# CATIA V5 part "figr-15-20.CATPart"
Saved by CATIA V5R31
Part number: Part1
Bounding box of the stored display mesh (mm): x -81.56 to 85.56, y -36.965 to 25.965, z 0 to 42
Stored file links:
  D:\PROJECTS\Project 2021\US EDITION\CATIA V5 6R 2021\Resources\Part Files\c15_catia_v5_6r2021_prt\figr-15-20.CATPart
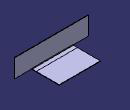
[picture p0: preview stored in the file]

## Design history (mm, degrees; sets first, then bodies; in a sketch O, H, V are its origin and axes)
SheetMetalParameters1: Thickness 1, BendRadius 1, KFactor 0.325257 {= log(min(100,max(20*SheetMetalParameters1.BendRadius,SheetMetalParameters1.Thickness)/SheetMetalParameters1.Thickness))/log(100)/2}, ReliefRadialLength 1, ReliefAxialLength 2, MinimumBendRadius 0
Body1 (main body)
  Sketch1 on xy-plane, origin (0, 0, 0), H (1, 0, 0), V (0, 1, 0)
    line L1 (-46.5596, 25.9646) -> (46.5596, 25.9646)
    line L2 (46.5596, 25.9646) -> (46.5596, -25.9646)
    line L3 (46.5596, -25.9646) -> (-46.5596, -25.9646)
    line L4 (-46.5596, -25.9646) -> (-46.5596, 25.9646)
    horizontal: L1 H, L3 H
    vertical: L2 V, L4 V
    symmetry: L1 L3 H, L4 L2 V
  Wall1: Thickness 1, Profile Sketch1
  d_NewWallOnEdge1: NewWallOnEdge_Edge edge [face of Wall1 | face of Wall1], NewWallOnEdge_Length 42, NewWallOnEdge_HeightLimitOffset 0, NewWallOnEdge_WidthOffset1 39, NewWallOnEdge_WidthOffset2 35, NewWallOnEdge_Angle 90, NewWallOnEdge_BendRadiusValue 1 {= SheetMetalParameters1.BendRadius}, NewWallOnEdge_BendTable SheetMetalParameters1, KFacteur 0.325257 {= log(min(100,max(20*d_NewWallOnEdge1.Radius,SheetMetalParameters1.Thickness)/SheetMetalParameters1.Thickness))/log(100)/2}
